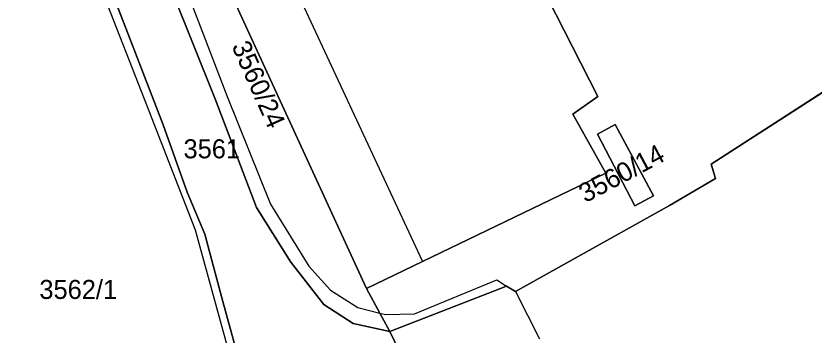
# Model space of a CAD drawing. Extents: x -262657 to -261595, y -1238015 to -1237156.
# Drawn here: x -262558.2 to -262474.2, y -1237334.5 to -1237300.9 of the extents above; entities that cross this region are included whole.
import ezdxf

# ---------------------------------------------------------------- set-up
doc = ezdxf.new("R2010")
doc.units = 0
for name, color, linetype in [('body_kn', 7, 'Continuous'), ('kladpar_druhypozemkov', 7, 'Continuous'), ('kladpar_hranice', 7, 'Continuous'), ('kladpar_parcelnecisla', 7, 'Continuous'), ('kladpar_plochy', 7, 'Continuous'), ('zappar_hrandruhpozemk', 7, 'Continuous')]:
    doc.layers.add(name, color=color, linetype=linetype)

msp = doc.modelspace()

# ---------------------------------------------------------------- linework, layer by layer
at = {"layer": 'body_kn'}
for p, q in [((-262535.97, -1237309.42), (-262535.97, -1237309.42)), ((-262496.96, -1237309.42), (-262496.96, -1237309.42)), ((-262544.72, -1237309.65), (-262544.72, -1237309.65)), ((-262537.2, -1237309.76), (-262537.2, -1237309.76)), ((-262499.6, -1237311.25), (-262499.6, -1237311.25)), ((-262542.72, -1237312.39), (-262542.72, -1237312.39)), ((-262495.13, -1237312.37), (-262495.13, -1237312.37)), ((-262496.99, -1237313.37), (-262496.99, -1237313.37)), ((-262496.99, -1237313.37), (-262496.99, -1237313.37)), ((-262485.02, -1237316.52), (-262485.02, -1237316.52)), ((-262496.12, -1237317.47), (-262496.12, -1237317.47)), ((-262484.59, -1237318.04), (-262484.59, -1237318.04)), ((-262540.2, -1237319.46), (-262540.2, -1237319.46)), ((-262491.1, -1237319.87), (-262491.1, -1237319.87)), ((-262532.89, -1237321.1), (-262532.89, -1237321.1)), ((-262531.44, -1237320.74), (-262531.44, -1237320.74)), ((-262493.07, -1237320.9), (-262493.07, -1237320.9)), ((-262489.43, -1237320.89), (-262489.43, -1237320.89)), ((-262539.37, -1237323.43), (-262539.37, -1237323.43)), ((-262538.34, -1237323.9), (-262538.34, -1237323.9)), ((-262529.29, -1237326.85), (-262529.29, -1237326.85)), ((-262527.4, -1237327.24), (-262527.4, -1237327.24)), ((-262515.41, -1237326.75), (-262515.41, -1237326.75)), ((-262507.61, -1237328.69), (-262507.61, -1237328.69)), ((-262521.33, -1237329.6), (-262521.33, -1237329.6)), ((-262521.33, -1237329.6), (-262521.33, -1237329.6)), ((-262506.56, -1237329.35), (-262506.56, -1237329.35)), ((-262536.56, -1237330.58), (-262536.56, -1237330.58)), ((-262525.09, -1237329.79), (-262525.09, -1237329.79)), ((-262505.64, -1237329.92), (-262505.64, -1237329.92)), ((-262505.64, -1237329.92), (-262505.64, -1237329.92)), ((-262525.82, -1237331.27), (-262525.82, -1237331.27)), ((-262522.24, -1237331.6), (-262522.24, -1237331.6)), ((-262519.91, -1237332.2), (-262519.91, -1237332.2)), ((-262519.91, -1237332.2), (-262519.91, -1237332.2)), ((-262516.26, -1237332.25), (-262516.26, -1237332.25)), ((-262519.32, -1237332.35), (-262519.32, -1237332.35)), ((-262522.72, -1237333.28), (-262522.72, -1237333.28)), ((-262518.85, -1237334.11), (-262518.85, -1237334.11))]:
    msp.add_line(p, q, dxfattribs=at)
at = {"layer": 'kladpar_druhypozemkov'}
for p, q in [((-262537.03, -1237301.49), (-262537.03, -1237301.49)), ((-262538.49, -1237314.06), (-262538.49, -1237314.06)), ((-262494.41, -1237316.01), (-262494.41, -1237316.01)), ((-262551.16, -1237328.06), (-262551.16, -1237328.06))]:
    msp.add_line(p, q, dxfattribs=at)
at = {"layer": 'kladpar_hranice'}
for points in [[(-262574.37, -1237249.46), (-262568.63, -1237248.12), (-262568.05, -1237247.91), (-262567.35, -1237249.24), (-262566.74, -1237250.59), (-262564.55, -1237256.82), (-262558.85, -1237270.72), (-262552.98, -1237286.01), (-262550.94, -1237291.12), (-262542.72, -1237312.39), (-262540.2, -1237319.46), (-262538.34, -1237323.9), (-262536.56, -1237330.58), (-262531.33, -1237349.62), (-262532.04, -1237349.98), (-262533.34, -1237350.65), (-262556.43, -1237362.71), (-262558.44, -1237358.79), (-262564.27, -1237347.05)], [(-262544.97, -1237277.21), (-262547.68, -1237283.68), (-262541.83, -1237298.18), (-262537.2, -1237309.76), (-262532.89, -1237321.1), (-262529.29, -1237326.85), (-262525.82, -1237331.27), (-262522.72, -1237333.28), (-262518.85, -1237334.11), (-262515.3, -1237341.44), (-262526.44, -1237347.1), (-262531.33, -1237349.62), (-262536.56, -1237330.58), (-262538.34, -1237323.9), (-262540.2, -1237319.46), (-262542.72, -1237312.39), (-262550.94, -1237291.12), (-262552.98, -1237286.01), (-262558.85, -1237270.72), (-262564.55, -1237256.82), (-262566.74, -1237250.59)], [(-262470.96, -1237307.46), (-262485.02, -1237316.52), (-262484.59, -1237318.04), (-262489.43, -1237320.89), (-262505.64, -1237329.92), (-262506.56, -1237329.35), (-262518.85, -1237334.11), (-262519.91, -1237332.2), (-262521.33, -1237329.6), (-262515.41, -1237326.75), (-262496.12, -1237317.47), (-262499.6, -1237311.25), (-262496.96, -1237309.42), (-262513.79, -1237276.37), (-262515.86, -1237276.71), (-262520.5, -1237266.83), (-262537.33, -1237275.21), (-262538.53, -1237277.21), (-262540.98, -1237281.3), (-262540.97, -1237288.14), (-262543.4, -1237280.99), (-262544.97, -1237277.21)], [(-262521.33, -1237329.6), (-262535.24, -1237299.36), (-262540.97, -1237288.14), (-262540.98, -1237281.3), (-262538.53, -1237277.21), (-262537.33, -1237275.21), (-262520.5, -1237266.83), (-262515.86, -1237276.71), (-262513.79, -1237276.37), (-262496.96, -1237309.42), (-262499.6, -1237311.25), (-262496.12, -1237317.47), (-262515.41, -1237326.75), (-262521.33, -1237329.6)], [(-262521.33, -1237329.6), (-262519.91, -1237332.2), (-262518.85, -1237334.11), (-262522.72, -1237333.28), (-262525.82, -1237331.27), (-262529.29, -1237326.85), (-262532.89, -1237321.1), (-262537.2, -1237309.76), (-262541.83, -1237298.18), (-262547.68, -1237283.68), (-262544.97, -1237277.21), (-262543.4, -1237280.99), (-262540.97, -1237288.14), (-262535.24, -1237299.36), (-262521.33, -1237329.6)], [(-262473.2, -1237359.19), (-262481.99, -1237363.24), (-262483.1, -1237361.34), (-262488.5, -1237364.1), (-262489.25, -1237362.09), (-262491.55, -1237358.01), (-262499.53, -1237342.25), (-262501.74, -1237343.49), (-262505.16, -1237337.44), (-262510.07, -1237339.8), (-262513.59, -1237341.73), (-262514.06, -1237340.81), (-262515.3, -1237341.44), (-262518.85, -1237334.11), (-262506.56, -1237329.35), (-262505.64, -1237329.92), (-262489.43, -1237320.89), (-262484.59, -1237318.04), (-262485.02, -1237316.52), (-262470.96, -1237307.46)], [(-262495.13, -1237312.37), (-262496.99, -1237313.37), (-262493.07, -1237320.9), (-262491.1, -1237319.87), (-262495.13, -1237312.37)], [(-262496.99, -1237313.37), (-262495.13, -1237312.37), (-262491.1, -1237319.87), (-262493.07, -1237320.9), (-262496.99, -1237313.37)]]:
    msp.add_lwpolyline(points, dxfattribs=at)
at = {"layer": 'kladpar_plochy'}
for p, q in [((-262496.96, -1237309.42), (-262513.79, -1237276.37)), ((-262550.94, -1237291.12), (-262542.72, -1237312.39)), ((-262470.96, -1237307.46), (-262485.02, -1237316.52)), ((-262485.02, -1237316.52), (-262470.96, -1237307.46)), ((-262499.6, -1237311.25), (-262496.96, -1237309.42)), ((-262496.12, -1237317.47), (-262499.6, -1237311.25)), ((-262542.72, -1237312.39), (-262540.2, -1237319.46)), ((-262495.13, -1237312.37), (-262496.99, -1237313.37)), ((-262491.1, -1237319.87), (-262495.13, -1237312.37)), ((-262496.99, -1237313.37), (-262493.07, -1237320.9)), ((-262485.02, -1237316.52), (-262484.59, -1237318.04)), ((-262484.59, -1237318.04), (-262485.02, -1237316.52)), ((-262515.41, -1237326.75), (-262496.12, -1237317.47)), ((-262484.59, -1237318.04), (-262489.43, -1237320.89)), ((-262489.43, -1237320.89), (-262484.59, -1237318.04)), ((-262540.2, -1237319.46), (-262538.34, -1237323.9)), ((-262493.07, -1237320.9), (-262491.1, -1237319.87)), ((-262489.43, -1237320.89), (-262505.64, -1237329.92)), ((-262505.64, -1237329.92), (-262489.43, -1237320.89)), ((-262538.34, -1237323.9), (-262536.56, -1237330.58)), ((-262521.33, -1237329.6), (-262515.41, -1237326.75)), ((-262519.91, -1237332.2), (-262521.33, -1237329.6)), ((-262506.56, -1237329.35), (-262518.85, -1237334.11)), ((-262518.85, -1237334.11), (-262506.56, -1237329.35)), ((-262505.64, -1237329.92), (-262506.56, -1237329.35)), ((-262506.56, -1237329.35), (-262505.64, -1237329.92)), ((-262536.56, -1237330.58), (-262531.33, -1237349.62)), ((-262518.85, -1237334.11), (-262519.91, -1237332.2)), ((-262515.3, -1237341.44), (-262518.85, -1237334.11))]:
    msp.add_line(p, q, dxfattribs=at)
msp.add_lwpolyline([(-262563.3, -1237255.68), (-262556.86, -1237260.6), (-262550.52, -1237263.55), (-262546.64, -1237272.98), (-262544.97, -1237277.21), (-262547.68, -1237283.68), (-262541.83, -1237298.18), (-262537.2, -1237309.76), (-262532.89, -1237321.1), (-262529.29, -1237326.85), (-262525.82, -1237331.27), (-262522.72, -1237333.28), (-262518.85, -1237334.11), (-262515.3, -1237341.44), (-262526.44, -1237347.1), (-262531.33, -1237349.62), (-262536.56, -1237330.58), (-262538.34, -1237323.9), (-262540.2, -1237319.46), (-262542.72, -1237312.39), (-262550.94, -1237291.12), (-262552.98, -1237286.01), (-262558.85, -1237270.72)], dxfattribs=at)
for points in [[(-262521.33, -1237329.6), (-262535.24, -1237299.36), (-262540.97, -1237288.14), (-262540.98, -1237281.3), (-262538.53, -1237277.21), (-262537.33, -1237275.21), (-262520.5, -1237266.83), (-262515.86, -1237276.71), (-262513.79, -1237276.37), (-262496.96, -1237309.42), (-262499.6, -1237311.25), (-262496.12, -1237317.47), (-262515.41, -1237326.75)], [(-262521.33, -1237329.6), (-262519.91, -1237332.2), (-262518.85, -1237334.11), (-262522.72, -1237333.28), (-262525.82, -1237331.27), (-262529.29, -1237326.85), (-262532.89, -1237321.1), (-262537.2, -1237309.76), (-262541.83, -1237298.18), (-262547.68, -1237283.68), (-262544.97, -1237277.21), (-262543.4, -1237280.99), (-262540.97, -1237288.14), (-262535.24, -1237299.36)], [(-262496.99, -1237313.37), (-262495.13, -1237312.37), (-262491.1, -1237319.87), (-262493.07, -1237320.9)]]:
    msp.add_lwpolyline(points, close=True, dxfattribs=at)
at = {"layer": 'zappar_hrandruhpozemk'}
for p, q in [((-262538.53, -1237277.21), (-262515.41, -1237326.75)), ((-262556.56, -1237279.36), (-262544.72, -1237309.65)), ((-262516.26, -1237332.25), (-262507.61, -1237328.69)), ((-262507.61, -1237328.69), (-262506.56, -1237329.35)), ((-262505.64, -1237329.92), (-262503.11, -1237334.88))]:
    msp.add_line(p, q, dxfattribs=at)
for points in [[(-262544.85, -1237286.26), (-262535.97, -1237309.42), (-262531.44, -1237320.74)], [(-262544.72, -1237309.65), (-262539.37, -1237323.43), (-262532.04, -1237349.98)], [(-262531.44, -1237320.74), (-262527.4, -1237327.24), (-262525.09, -1237329.79), (-262522.24, -1237331.6), (-262519.91, -1237332.2)], [(-262519.91, -1237332.2), (-262519.32, -1237332.35), (-262516.26, -1237332.25)]]:
    msp.add_lwpolyline(points, dxfattribs=at)

# ---------------------------------------------------------------- texts
at = {"layer": 'kladpar_parcelnecisla'}
for s, rotation, p in [('3560/24', 294, (-262535.548, -1237304.113)), ('3561', 360, (-262540.578, -1237315.91)), ('3560/14', 28, (-262498.274, -1237320.637))]:
    msp.add_text(s, height=2, rotation=rotation, dxfattribs=at).set_placement(p)
msp.add_text('3562/1', height=2, dxfattribs=at).set_placement((-262555.755, -1237330.7))

doc.saveas('drawing.dxf')
